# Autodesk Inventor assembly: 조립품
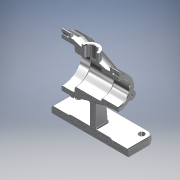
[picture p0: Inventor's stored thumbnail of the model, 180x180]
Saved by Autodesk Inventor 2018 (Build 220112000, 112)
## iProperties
Created: 2020-03
Part Number: 조립품
Document SubType Name: Assembly
Designer: Administrator
Author: Administrator
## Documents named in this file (2)
- C:\Users\Administrator\Desktop\700306V1014\조립품.iam
- C:\Users\Administrator\Desktop\700306V1014\본체.ipt
